(* Logix 5000 project; controller HARDY_HI6501_Sample_V30_R2_1 vendor 1 type 14 code 196 rev 30.17; software revision 30.00 *)

TASK MainTask (continuous, watchdog 500 ms) : MainProgram, HARDY_HI6501_Scale_0

MODULES
   Local : vendor 1 type 14 code 196 (5069 0, rev 30.17)
      HARDY_HI6501_Scale_0 : vendor 258 type 43 code 15 (Ethernet 192.168.1.4, rev 2.92, StandardDataDriven RPI 20 ms)
END_MODULES

PROGRAM HARDY_HI6501_Scale_0   (* main routine MainRoutine *)
VAR
   C2_Cal_Scale : BOOL;
   C2_Scale_ONS1 : BOOL;
   C2_Search : BOOL;
   C2_Search_ONS1 : BOOL;
   C2UnlatchONS1 : BOOL;
   Command_Reset_TON1 : TIMER := (PRE := 2000);
   Gross_Weight_Display_1DecPt : REAL;
   Gross_Wt_x10_DINT : DINT;
   HI6501_Gross_Weight_Display : REAL;
   HI6501_Heartbeat_Display : INT := 24960;
   HI6501_Net_Weight_Display : REAL;
   Last_Command_Sent : INT := 102;
   Last_Command_Status_Hex : INT := 16#ab00;
   Set_Default_Params : BOOL;
   SetDefault_ONS1 : BOOL;
   Tare_Scale : BOOL;
   Tare_Scale_ONS1 : BOOL;
   TradCalHigh_ONS1 : BOOL;
   TradCalLow_ONS1 : BOOL;
   Traditional_Cal_High : BOOL;
   Traditional_Cal_Low : BOOL;
   Zero_Scale : BOOL;
   Zero_Scale_ONS1 : BOOL;
END_VAR

ROUTINE MainRoutine   (* ladder *)
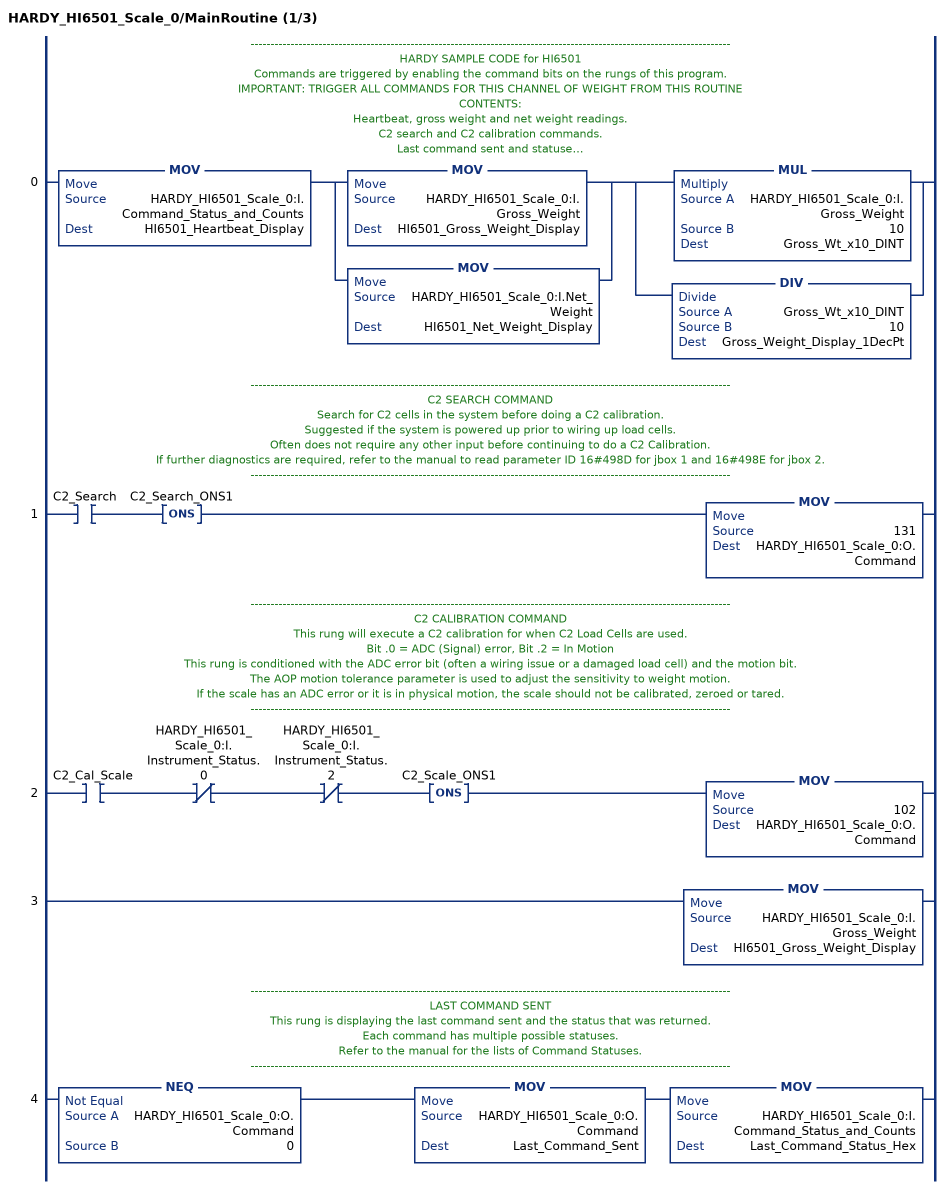
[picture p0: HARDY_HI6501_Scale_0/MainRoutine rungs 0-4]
   // ------------------------------------------------------------------------------------------------------------------------
   // HARDY SAMPLE CODE for HI6501
   // Commands are triggered by enabling the command bits on the rungs of this program.
   // IMPORTANT: TRIGGER ALL COMMANDS FOR THIS CHANNEL OF WEIGHT FROM THIS ROUTINE
   // CONTENTS:
   // Heartbeat, gross weight and net weight readings.
   // C2 search and C2 calibration commands.
   // Last command sent and statuses
   // Zero, Tare and other commands.
   // It is recommended to configure the parameters via the AOP prior to sending commands.
   // This is a display rung for the channel heartbeat, weight readings and an example of reducing the displayed number of decimal points.
   // ------------------------------------------------------------------------------------------------------------------------
   0: MOV(HARDY_HI6501_Scale_0:I.Command_Status_and_Counts,HI6501_Heartbeat_Display)[MOV(HARDY_HI6501_Scale_0:I.Gross_Weight,HI6501_Gross_Weight_Display) ,MOV(HARDY_HI6501_Scale_0:I.Net_Weight,HI6501_Net_Weight_Display) ][MUL(HARDY_HI6501_Scale_0:I.Gross_Weight,10,Gross_Wt_x10_DINT) ,DIV(Gross_Wt_x10_DINT,10,Gross_Weight_Display_1DecPt) ];
   // ------------------------------------------------------------------------------------------------------------------------
   // C2 SEARCH COMMAND
   // Search for C2 cells in the system before doing a C2 calibration.
   // Suggested if the system is powered up prior to wiring up load cells.
   // Often does not require any other input before continuing to do a C2 Calibration.
   // If further diagnostics are required, refer to the manual to read parameter ID 16#498D for jbox 1 and 16#498E for jbox 2.
   // ------------------------------------------------------------------------------------------------------------------------
   1: XIC(C2_Search)ONS(C2_Search_ONS1)MOV(131,HARDY_HI6501_Scale_0:O.Command);
   // ------------------------------------------------------------------------------------------------------------------------
   // C2 CALIBRATION COMMAND
   // This rung will execute a C2 calibration for when C2 Load Cells are used.
   // Bit .0 = ADC (Signal) error, Bit .2 = In Motion
   // This rung is conditioned with the ADC error bit (often a wiring issue or a damaged load cell) and the motion bit.
   // The AOP motion tolerance parameter is used to adjust the sensitivity to weight motion.
   // If the scale has an ADC error or it is in physical motion, the scale should not be calibrated, zeroed or tared.
   // ------------------------------------------------------------------------------------------------------------------------
   2: XIC(C2_Cal_Scale)XIO(HARDY_HI6501_Scale_0:I.Instrument_Status.0)XIO(HARDY_HI6501_Scale_0:I.Instrument_Status.2)ONS(C2_Scale_ONS1)MOV(102,HARDY_HI6501_Scale_0:O.Command);
   3: MOV(HARDY_HI6501_Scale_0:I.Gross_Weight,HI6501_Gross_Weight_Display);
   // ------------------------------------------------------------------------------------------------------------------------
   // LAST COMMAND SENT
   // This rung is displaying the last command sent and the status that was returned.
   // Each command has multiple possible statuses.
   // Refer to the manual for the lists of Command Statuses.
   // ------------------------------------------------------------------------------------------------------------------------
   4: NEQ(HARDY_HI6501_Scale_0:O.Command,0)MOV(HARDY_HI6501_Scale_0:O.Command,Last_Command_Sent)MOV(HARDY_HI6501_Scale_0:I.Command_Status_and_Counts,Last_Command_Status_Hex);
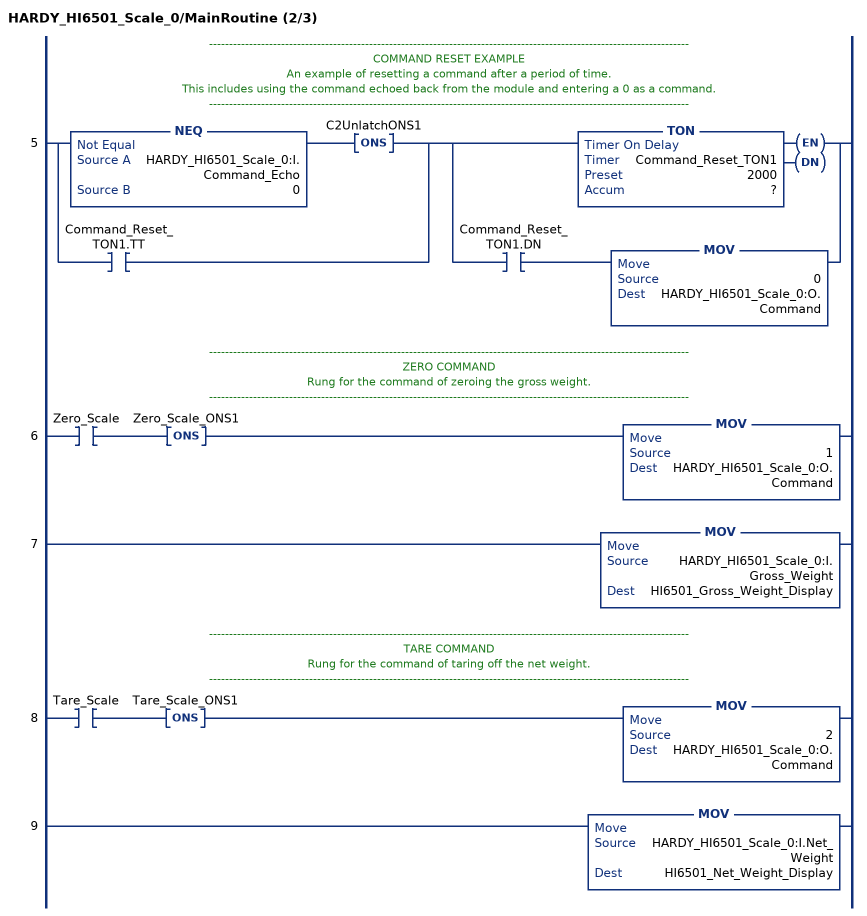
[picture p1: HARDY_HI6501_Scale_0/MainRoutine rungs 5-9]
   // ------------------------------------------------------------------------------------------------------------------------
   // COMMAND RESET EXAMPLE
   // An example of resetting a command after a period of time.
   // This includes using the command echoed back from the module and entering a 0 as a command.
   // ------------------------------------------------------------------------------------------------------------------------
   5: [NEQ(HARDY_HI6501_Scale_0:I.Command_Echo,0) ONS(C2UnlatchONS1) ,XIC(Command_Reset_TON1.TT) ][TON(Command_Reset_TON1,?,?) ,XIC(Command_Reset_TON1.DN) MOV(0,HARDY_HI6501_Scale_0:O.Command) ];
   // ------------------------------------------------------------------------------------------------------------------------
   // ZERO COMMAND
   // Rung for the command of zeroing the gross weight.
   // ------------------------------------------------------------------------------------------------------------------------
   6: XIC(Zero_Scale)ONS(Zero_Scale_ONS1)MOV(1,HARDY_HI6501_Scale_0:O.Command);
   7: MOV(HARDY_HI6501_Scale_0:I.Gross_Weight,HI6501_Gross_Weight_Display);
   // ------------------------------------------------------------------------------------------------------------------------
   // TARE COMMAND
   // Rung for the command of taring off the net weight.
   // ------------------------------------------------------------------------------------------------------------------------
   8: XIC(Tare_Scale)ONS(Tare_Scale_ONS1)MOV(2,HARDY_HI6501_Scale_0:O.Command);
   9: MOV(HARDY_HI6501_Scale_0:I.Net_Weight,HI6501_Net_Weight_Display);
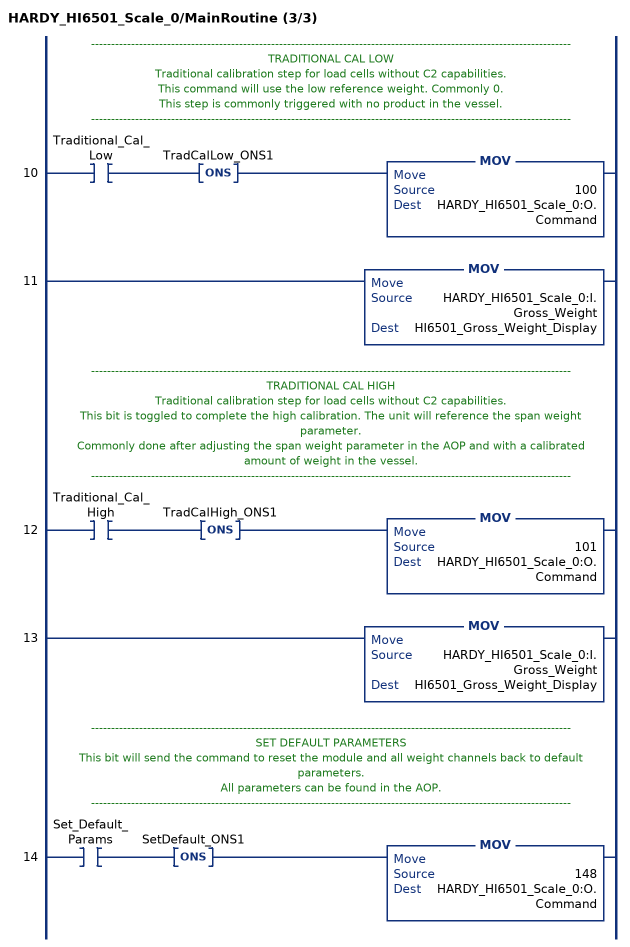
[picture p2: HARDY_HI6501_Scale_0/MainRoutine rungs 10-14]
   // ------------------------------------------------------------------------------------------------------------------------
   // TRADITIONAL CAL LOW
   // Traditional calibration step for load cells without C2 capabilities.
   // This command will use the low reference weight. Commonly 0.
   // This step is commonly triggered with no product in the vessel.
   // ------------------------------------------------------------------------------------------------------------------------
   10: XIC(Traditional_Cal_Low)ONS(TradCalLow_ONS1)MOV(100,HARDY_HI6501_Scale_0:O.Command);
   11: MOV(HARDY_HI6501_Scale_0:I.Gross_Weight,HI6501_Gross_Weight_Display);
   // ------------------------------------------------------------------------------------------------------------------------
   // TRADITIONAL CAL HIGH
   // Traditional calibration step for load cells without C2 capabilities.
   // This bit is toggled to complete the high calibration. The unit will reference the span weight parameter.
   // Commonly done after adjusting the span weight parameter in the AOP and with a calibrated amount of weight in the vessel.
   // ------------------------------------------------------------------------------------------------------------------------
   12: XIC(Traditional_Cal_High)ONS(TradCalHigh_ONS1)MOV(101,HARDY_HI6501_Scale_0:O.Command);
   13: MOV(HARDY_HI6501_Scale_0:I.Gross_Weight,HI6501_Gross_Weight_Display);
   // ------------------------------------------------------------------------------------------------------------------------
   // SET DEFAULT PARAMETERS
   // This bit will send the command to reset the module and all weight channels back to default parameters.
   // All parameters can be found in the AOP.
   // ------------------------------------------------------------------------------------------------------------------------
   14: XIC(Set_Default_Params)ONS(SetDefault_ONS1)MOV(148,HARDY_HI6501_Scale_0:O.Command);
END_ROUTINE
END_PROGRAM

PROGRAM MainProgram   (* main routine MainRoutine *)

ROUTINE MainRoutine   (* ladder *)
END_ROUTINE
END_PROGRAM
